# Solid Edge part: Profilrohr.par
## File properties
Username: bmolnar
Dokumentum tartalom típus: 0
Author: bmolnar
Last saved by: bmolnar
Revision: 79
Sűrűség: 0,000 kg/m^3
Pontosság: 0,990
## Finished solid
Body 1: solid body, 63 faces, 178 edges, 112 vertices.
  Faces by surface: cylinder 33, plane 30
  Edges by curve: line 112, circle 66
Bounding box of the edges (mm): 36.000 x 28.400 x 36.000, from (-18, -19.15, -18) to (18, 9.25, 18).
Cylindrical faces by radius (mm): R0.2 x12, R0.5 x12, R3.775 x4, R4.5 x4, R10 x1
Planar faces by outward normal: +x 7, +y 1, +z 7, -x 7, -y 1, -z 7
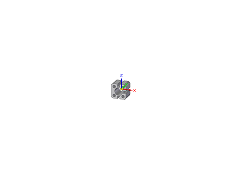
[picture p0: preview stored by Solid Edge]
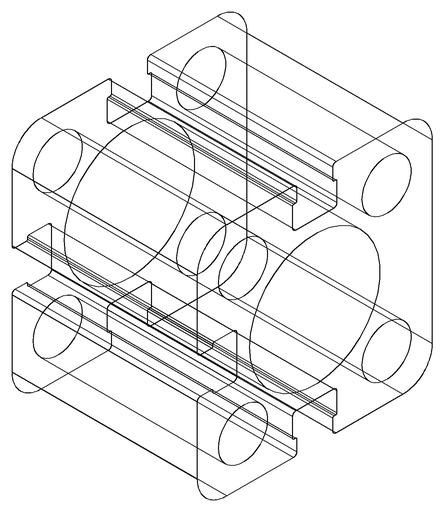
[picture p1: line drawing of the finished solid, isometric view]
